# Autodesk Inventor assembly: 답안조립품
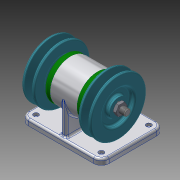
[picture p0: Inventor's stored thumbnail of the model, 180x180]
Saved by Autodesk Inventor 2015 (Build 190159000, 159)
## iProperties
Created: 2019-09
Part Number: 답안조립품
Document SubType Name: Assembly
Designer: Lineart
Author: Lineart
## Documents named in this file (10)
- C:\Users\Lineart\Desktop\490904V1055\답안조립품.iam
- C:\Users\Lineart\Desktop\490904V1055\본체.ipt
- C:\Users\Lineart\Desktop\490904V1055\볼트 M4.ipt
- C:\Users\Lineart\Desktop\490904V1055\V-벨트풀리.ipt
- C:\Users\Lineart\Desktop\490904V1055\베어링 6004.ipt
- C:\Users\Lineart\Desktop\490904V1055\오일 실 17 30 5.ipt
- C:\Users\Lineart\Desktop\490904V1055\축.ipt
- C:\Users\Lineart\Desktop\490904V1055\커버.ipt
- C:\Users\Lineart\Desktop\490904V1055\키 5 x 5 x 12.ipt
- C:\Users\Lineart\Desktop\490904V1055\너트 M10x1.ipt
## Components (2 placed, 1 different names)
1. V-벨트풀리:1 — 각도:2
2. V-벨트풀리:2 — 각도:7
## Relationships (2: Angle 2)
- 각도:2 [Angle]: V-벨트풀리:1
- 각도:7 [Angle]: V-벨트풀리:2
